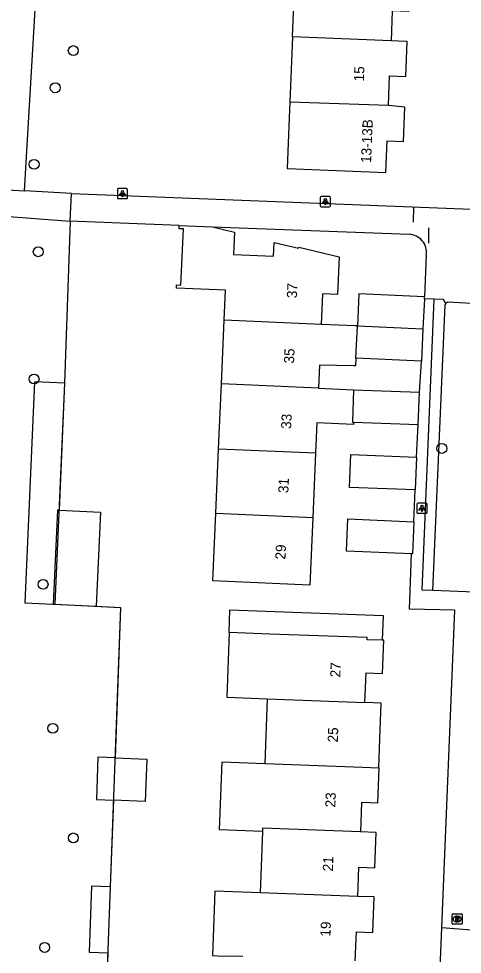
# Model space of a CAD drawing. Extents: x 160732 to 162105, y 387428 to 388479.
# Drawn here: x 161061 to 161104.8, y 387524.9 to 387617.3 of the extents above; entities that cross this region are included whole.
import ezdxf

# ---------------------------------------------------------------- set-up
doc = ezdxf.new("R2010")
doc.units = 0
for name, color, linetype in [('IMGEO_Boom', 7, 'Continuous'), ('IMGEO_Brandkraan', 7, 'Continuous'), ('IMGEO_Groenvoorziening', 7, 'Continuous'), ('IMGEO_Hek', 7, 'Continuous'), ('IMGEO_Lichtpunt', 7, 'Continuous'), ('IMGEO_Loofbos', 7, 'Continuous'), ('IMGEO_Pand', 7, 'Continuous'), ('IMGEO_Pand_nummerreeks', 7, 'Continuous'), ('IMGEO_Voetpad_gesloten', 7, 'Continuous'), ('IMGEO_Voetpad_open', 7, 'Continuous')]:
    doc.layers.add(name, color=color, linetype=linetype)

msp = doc.modelspace()

# ---------------------------------------------------------------- linework, layer by layer
at = {"layer": 'IMGEO_Boom'}
for centre in [(161066.406, 387614.144), (161064.624, 387610.472), (161062.539, 387602.915), (161062.949, 387594.29), (161062.537, 387581.726), (161102.793, 387574.878), (161063.426, 387561.461), (161064.383, 387547.254), (161066.412, 387536.432), (161063.577, 387525.619)]:
    msp.add_circle(centre, 0.489, dxfattribs=at)
at = {"layer": 'IMGEO_Brandkraan'}
for p, q in [((161103.805, 387527.999), (161103.805, 387528.851)), ((161103.88, 387528.925), (161104.732, 387528.925)), ((161104.316, 387528.145), (161104.291, 387528.145)), ((161104.293, 387528.705), (161104.318, 387528.705)), ((161104.806, 387528.851), (161104.806, 387527.999)), ((161104.732, 387527.925), (161103.88, 387527.925))]:
    msp.add_line(p, q, dxfattribs=at)
for points in [[(161103.805, 387527.999), (161103.805, 387528.851)], [(161103.88, 387528.925), (161104.732, 387528.925)], [(161104.153, 387528.625), (161104.153, 387528.225), (161104.366, 387528.225)], [(161104.384, 387528.625), (161104.153, 387528.625)], [(161104.332, 387528.544), (161104.278, 387528.544), (161104.278, 387528.468)], [(161104.278, 387528.468), (161104.331, 387528.468)], [(161104.34, 387528.392), (161104.278, 387528.392), (161104.278, 387528.311)], [(161104.278, 387528.311), (161104.34, 387528.311)], [(161104.806, 387528.851), (161104.806, 387527.999)], [(161104.732, 387527.925), (161103.88, 387527.925)]]:
    msp.add_lwpolyline(points, dxfattribs=at)
for centre, radius, start, end in [((161103.882, 387528.849), 0.0765, 91.55205, 178.44795), ((161103.882, 387528.849), 0.0765, 91.55205, 178.44795), ((161104.333, 387528.506), 0.0379, 267.82845, 90.93552), ((161104.341, 387528.351), 0.0404, 269.87594, 90.50774), ((161104.372, 387528.476), 0.251, 268.66757, 293.53466), ((161104.388, 387528.48), 0.145, 59.4692, 91.53667), ((161104.413, 387528.527), 0.0922, 285.51372, 58.15012), ((161104.418, 387528.335), 0.105, 301.31148, 78.98903), ((161104.73, 387528.849), 0.0765, 1.55205, 88.44795), ((161104.73, 387528.849), 0.0765, 1.55205, 88.44795), ((161103.882, 387528.001), 0.0765, 181.55205, 268.44795), ((161103.882, 387528.001), 0.0765, 181.55205, 268.44795), ((161104.73, 387528.001), 0.0765, 271.55205, 358.44795), ((161104.73, 387528.001), 0.0765, 271.55205, 358.44795)]:
    msp.add_arc(centre, radius, start, end, dxfattribs=at)
for centre, major_axis, ratio, start_param, end_param in [((161104.292, 387528.425), (-0.387, 0.002), 0.722429, 4.712389, 7.853982), ((161104.317, 387528.425), (-0.39, 0.002), 0.717154, 1.570796, 4.712389)]:
    msp.add_ellipse(centre, major_axis=major_axis, ratio=ratio, start_param=start_param, end_param=end_param, dxfattribs=at)
at = {"layer": 'IMGEO_Groenvoorziening'}
for points in [[(161066.088, 387597.32), (161065.553, 387581.331)], [(161068.672, 387559.323), (161071.084, 387559.187), (161070.528, 387544.341)], [(161070.371, 387540.152), (161070.05, 387531.608), (161068.211, 387531.677), (161067.968, 387525.152), (161069.806, 387525.083), (161068.983, 387503.133), (161068.831, 387499.085), (161090.674, 387498.116), (161090.78, 387500.95), (161104.081, 387500.36)]]:
    msp.add_lwpolyline(points, dxfattribs=at)
at = {"layer": 'IMGEO_Hek'}
for points in [[(161100.006, 387598.724), (161099.972, 387597.211)], [(161066.088, 387597.32), (161065.553, 387581.331)], [(161101.474, 387596.655), (161101.468, 387595.126)], [(161065.553, 387581.331), (161064.601, 387559.501)], [(161064.601, 387559.501), (161071.084, 387559.187), (161068.983, 387503.133)]]:
    msp.add_lwpolyline(points, dxfattribs=at)
at = {"layer": 'IMGEO_Lichtpunt'}
for p, q in [((161070.758, 387600.432), (161070.758, 387599.625)), ((161070.758, 387600.432), (161070.758, 387599.625)), ((161071.66, 387600.527), (161070.852, 387600.527)), ((161071.66, 387600.527), (161070.852, 387600.527)), ((161071.754, 387599.625), (161071.754, 387600.432)), ((161071.754, 387599.625), (161071.754, 387600.432)), ((161070.852, 387599.531), (161071.66, 387599.531)), ((161070.852, 387599.531), (161071.66, 387599.531)), ((161090.792, 387599.637), (161090.792, 387598.83)), ((161090.792, 387599.637), (161090.792, 387598.83)), ((161091.694, 387599.732), (161090.886, 387599.732)), ((161091.694, 387599.732), (161090.886, 387599.732)), ((161091.788, 387598.83), (161091.788, 387599.637)), ((161091.788, 387598.83), (161091.788, 387599.637)), ((161090.886, 387598.736), (161091.694, 387598.736)), ((161090.886, 387598.736), (161091.694, 387598.736)), ((161100.335, 387569.374), (161100.335, 387568.567)), ((161100.335, 387569.374), (161100.335, 387568.567)), ((161101.237, 387569.469), (161100.429, 387569.469)), ((161101.237, 387569.469), (161100.429, 387569.469)), ((161101.331, 387568.567), (161101.331, 387569.374)), ((161101.331, 387568.567), (161101.331, 387569.374)), ((161100.429, 387568.473), (161101.237, 387568.473)), ((161100.429, 387568.473), (161101.237, 387568.473))]:
    msp.add_line(p, q, dxfattribs=at)
for points in [[(161071.132, 387600.096), (161071.171, 387600.068), (161070.983, 387599.806), (161070.945, 387599.833), (161071.132, 387600.096)], [(161071.234, 387600.048), (161071.281, 387600.048), (161071.281, 387599.726), (161071.234, 387599.726), (161071.234, 387600.048)], [(161071.344, 387600.068), (161071.382, 387600.095), (161071.569, 387599.833), (161071.53, 387599.805), (161071.344, 387600.068)], [(161091.166, 387599.301), (161091.205, 387599.273), (161091.017, 387599.011), (161090.979, 387599.038), (161091.166, 387599.301)], [(161091.268, 387599.253), (161091.315, 387599.253), (161091.315, 387598.931), (161091.268, 387598.931), (161091.268, 387599.253)], [(161091.378, 387599.273), (161091.416, 387599.3), (161091.603, 387599.038), (161091.564, 387599.01), (161091.378, 387599.273)], [(161100.709, 387569.038), (161100.748, 387569.01), (161100.56, 387568.748), (161100.522, 387568.775), (161100.709, 387569.038)], [(161100.811, 387568.99), (161100.858, 387568.99), (161100.858, 387568.668), (161100.811, 387568.668), (161100.811, 387568.99)], [(161100.921, 387569.01), (161100.959, 387569.037), (161101.146, 387568.775), (161101.107, 387568.747), (161100.921, 387569.01)]]:
    msp.add_lwpolyline(points, dxfattribs=at)
for centre in [(161071.257, 387600.23), (161091.291, 387599.435), (161100.834, 387569.172)]:
    msp.add_circle(centre, 0.0994, dxfattribs=at)
for centre, start, end in [((161070.852, 387600.432), 90, 180), ((161070.852, 387600.432), 90, 180), ((161071.66, 387600.432), 0, 90), ((161071.66, 387600.432), 0, 90), ((161070.852, 387599.625), 180, 270), ((161070.852, 387599.625), 180, 270), ((161071.66, 387599.625), 270, 0), ((161071.66, 387599.625), 270, 360), ((161090.886, 387599.637), 90, 180), ((161090.886, 387599.637), 90, 180), ((161091.694, 387599.637), 0, 90), ((161091.694, 387599.637), 0, 90), ((161090.886, 387598.83), 180, 270), ((161090.886, 387598.83), 180, 270), ((161091.694, 387598.83), 270, 0), ((161091.694, 387598.83), 270, 360), ((161100.429, 387569.374), 90, 180), ((161100.429, 387569.374), 90, 180), ((161101.237, 387569.374), 0, 90), ((161101.237, 387569.374), 0, 90), ((161100.429, 387568.567), 180, 270), ((161100.429, 387568.567), 180, 270), ((161101.237, 387568.567), 270, 0), ((161101.237, 387568.567), 270, 360)]:
    msp.add_arc(centre, 0.0946, start, end, dxfattribs=at)
at = {"layer": 'IMGEO_Loofbos'}
for points in [[(161061.574, 387600.31), (161064.492, 387649.589), (161066.023, 387688.174)], [(161065.553, 387581.331), (161062.574, 387581.461), (161061.624, 387559.645), (161064.436, 387559.509)], [(161065.553, 387581.331), (161065.006, 387568.78)]]:
    msp.add_lwpolyline(points, dxfattribs=at)
at = {"layer": 'IMGEO_Pand'}
for points in [[(161088.059, 387615.506), (161088.32, 387621.923)], [(161098.006, 387621.54), (161099.641, 387621.472), (161099.5, 387618.01), (161097.898, 387618.075), (161097.778, 387615.121)], [(161088.059, 387615.506), (161087.797, 387609.055)], [(161097.778, 387615.121), (161088.059, 387615.506)], [(161097.522, 387608.713), (161097.641, 387611.641), (161099.239, 387611.576), (161099.38, 387615.056), (161098.526, 387615.091), (161097.778, 387615.121)], [(161087.797, 387609.055), (161087.734, 387607.517), (161087.531, 387602.521), (161097.268, 387602.125), (161097.395, 387605.243), (161098.998, 387605.178), (161099.136, 387608.576), (161097.522, 387608.713)], [(161097.522, 387608.713), (161087.797, 387609.055)], [(161081.306, 387587.539), (161081.435, 387590.486), (161076.597, 387590.699), (161076.611, 387591.023), (161077.041, 387591.004), (161077.284, 387596.538), (161076.854, 387596.557), (161076.869, 387596.887)], [(161076.869, 387596.887), (161080.141, 387596.743)], [(161080.141, 387596.743), (161082.311, 387596.23), (161082.214, 387594.024), (161086.183, 387593.849), (161086.242, 387595.197), (161088.646, 387594.629), (161088.669, 387594.726), (161092.659, 387593.783), (161092.497, 387590.081), (161091.025, 387590.146), (161090.892, 387587.119)], [(161101.084, 387589.83), (161094.612, 387590.142), (161094.458, 387586.963)], [(161101.074, 387589.627), (161100.932, 387586.679)], [(161101.074, 387589.627), (161101.084, 387589.83)], [(161081.029, 387581.243), (161081.306, 387587.539)], [(161090.892, 387587.119), (161081.306, 387587.539)], [(161094.458, 387586.963), (161094.236, 387586.973), (161090.892, 387587.119)], [(161094.305, 387583.787), (161094.458, 387586.963)], [(161094.458, 387586.963), (161100.932, 387586.679)], [(161100.932, 387586.679), (161100.777, 387583.475)], [(161094.305, 387583.787), (161094.268, 387583.021), (161094.063, 387583.025), (161090.715, 387583.085), (161090.615, 387580.822)], [(161100.777, 387583.475), (161094.305, 387583.787)], [(161080.748, 387574.847), (161081.029, 387581.243)], [(161090.615, 387580.822), (161081.029, 387581.243)], [(161090.615, 387580.822), (161094.082, 387580.669)], [(161094.082, 387580.669), (161093.957, 387577.456), (161094.07, 387577.452)], [(161094.082, 387580.669), (161100.577, 387580.417)], [(161100.452, 387577.204), (161100.577, 387580.417)], [(161094.07, 387577.452), (161094.061, 387577.232), (161090.464, 387577.39), (161090.334, 387574.427)], [(161100.452, 387577.204), (161094.07, 387577.452)], [(161080.468, 387568.488), (161080.748, 387574.847)], [(161080.748, 387574.847), (161090.334, 387574.427)], [(161090.334, 387574.427), (161090.054, 387568.067)], [(161100.17, 387570.785), (161093.675, 387571.029), (161093.797, 387574.275), (161100.292, 387574.031)], [(161100.292, 387574.031), (161100.17, 387570.785)], [(161065.006, 387568.78), (161064.844, 387568.787), (161064.436, 387559.509)], [(161065.006, 387568.78), (161069.079, 387568.601), (161068.672, 387559.323)], [(161090.054, 387568.067), (161089.76, 387561.379), (161080.174, 387561.8), (161080.468, 387568.488)], [(161080.468, 387568.488), (161090.054, 387568.067)], [(161099.793, 387564.467), (161093.388, 387564.739), (161093.522, 387567.913), (161100.033, 387567.637)], [(161100.033, 387567.637), (161099.898, 387564.463), (161099.793, 387564.467)], [(161064.436, 387559.509), (161068.672, 387559.323)], [(161081.788, 387556.707), (161081.87, 387558.931), (161096.992, 387558.371), (161096.902, 387555.946)], [(161081.788, 387556.707), (161081.551, 387550.316), (161085.563, 387550.167)], [(161096.902, 387555.946), (161095.421, 387556.001), (161095.428, 387556.201), (161085.8, 387556.558), (161081.788, 387556.707)], [(161095.198, 387549.81), (161095.306, 387552.723), (161096.929, 387552.663), (161097.05, 387555.94), (161096.902, 387555.946)], [(161085.563, 387550.167), (161085.325, 387543.772)], [(161085.563, 387550.167), (161095.198, 387549.81)], [(161096.575, 387543.353), (161096.682, 387546.224), (161096.813, 387549.75), (161095.198, 387549.81)], [(161070.528, 387544.341), (161068.841, 387544.404), (161068.685, 387540.215), (161070.371, 387540.152)], [(161070.528, 387544.341), (161073.67, 387544.223), (161073.513, 387540.035), (161070.371, 387540.152)], [(161085.076, 387537.065), (161080.858, 387537.222), (161081.106, 387543.929), (161085.325, 387543.772)], [(161085.325, 387543.772), (161094.96, 387543.413), (161096.575, 387543.353)], [(161096.575, 387543.353), (161096.452, 387539.876), (161094.861, 387539.936), (161094.754, 387537.043)], [(161094.754, 387537.043), (161085.089, 387537.404), (161085.076, 387537.065)], [(161085.076, 387537.065), (161084.852, 387531.023)], [(161094.5, 387530.665), (161094.607, 387533.556), (161096.191, 387533.498), (161096.321, 387536.985), (161094.754, 387537.043)], [(161084.852, 387531.023), (161080.375, 387531.189), (161080.138, 387524.814), (161080.638, 387524.806), (161083.138, 387524.767)], [(161094.5, 387530.665), (161084.852, 387531.023)], [(161094.246, 387524.289), (161094.353, 387527.169), (161095.98, 387527.108), (161096.11, 387530.605), (161094.5, 387530.665)]]:
    msp.add_lwpolyline(points, dxfattribs=at)
at = {"layer": 'IMGEO_Voetpad_gesloten'}
for points in [[(161049.031, 387595.743), (161049.233, 387601.041), (161061.574, 387600.31)], [(161066.224, 387600.035), (161061.574, 387600.31)], [(161066.088, 387597.32), (161066.224, 387600.035)], [(161051.995, 387580.571), (161052.673, 387598.338), (161066.088, 387597.32)]]:
    msp.add_lwpolyline(points, dxfattribs=at)
at = {"layer": 'IMGEO_Voetpad_open'}
for points in [[(161066.224, 387600.035), (161108.253, 387598.404)], [(161076.869, 387596.887), (161066.088, 387597.32)], [(161080.141, 387596.743), (161099.556, 387596.01)], [(161101.25, 387593.987), (161101.084, 387589.83)], [(161101.914, 387560.852), (161100.842, 387560.883), (161102.026, 387589.6)], [(161102.026, 387589.6), (161101.074, 387589.627)], [(161101.914, 387560.852), (161103.114, 387589.006), (161103.191, 387589.194)], [(161103.191, 387589.194), (161102.943, 387589.574), (161102.026, 387589.6)], [(161108.069, 387589.065), (161103.346, 387589.308), (161103.191, 387589.194)], [(161100.577, 387580.417), (161100.777, 387583.475)], [(161100.292, 387574.031), (161100.452, 387577.204)], [(161100.033, 387567.637), (161100.17, 387570.785)], [(161102.795, 387527.593), (161104.079, 387558.916), (161099.614, 387558.998), (161099.793, 387564.467)], [(161106.849, 387560.672), (161101.914, 387560.852)], [(161104.081, 387500.36), (161104.126, 387501.573), (161104.296, 387506.114), (161101.918, 387506.211), (161102.795, 387527.593)], [(161102.795, 387527.593), (161109.858, 387527.034)]]:
    msp.add_lwpolyline(points, dxfattribs=at)
msp.add_arc((161099.504, 387594.245), 1.765, 351.58156, 88.30205, dxfattribs=at)

# ---------------------------------------------------------------- texts
at = {"layer": 'IMGEO_Pand_nummerreeks'}
for s, rotation, p in [('15', 87.75089, (161095.098, 387611.088)), ('13-13B', 87.66827, (161095.804, 387603.037)), ('37', 87.48493, (161088.482, 387589.69)), ('35', 87.48493, (161088.198, 387583.24)), ('33', 87.48493, (161087.915, 387576.79)), ('31', 87.48246, (161087.636, 387570.453)), ('29', 87.48246, (161087.348, 387563.889)), ('27', 87.81151, (161092.763, 387552.261)), ('25', 87.81151, (161092.518, 387545.841)), ('23', 87.81151, (161092.273, 387539.422)), ('21', 87.81151, (161092.032, 387533.115)), ('19', 87.81151, (161091.787, 387526.674))]:
    msp.add_text(s, height=1, rotation=rotation, dxfattribs=at).set_placement(p)

doc.saveas('drawing.dxf')
